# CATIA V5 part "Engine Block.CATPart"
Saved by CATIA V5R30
Part number: Part1
Bounding box of the stored display mesh (mm): x 0 to 150, y 0 to 40, z 0 to 43
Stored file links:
  D:\PROJECTS\CATIA V56R 2020\Resources\Tutorial Files\c19_catia_v5_6r2019_tut\C19_tut_04.CATPart\Engine Block.CATPart
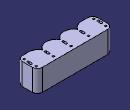
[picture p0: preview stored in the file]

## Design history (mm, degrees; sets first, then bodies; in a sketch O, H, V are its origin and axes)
Body1 (main body)
  Sketch1 on xy-plane, origin (0, 0, 0), H (1, 0, 0), V (0, 1, 0)
    line L1 (10, 0) -> (140, 0)
    line L2 (150, 10) -> (150, 30)
    line L3 (140, 40) -> (10, 40)
    line L4 (0, 30) -> (0, 10)
    arc A1 centre (10, 10) radius 10 from (10, 0) to (0, 10) cw
    arc A2 centre (140, 10) radius 10 from (140, 0) to (150, 10) ccw
    arc A3 centre (140, 30) radius 10 from (150, 30) to (140, 40) ccw
    arc A4 centre (10, 30) radius 10 from (10, 40) to (0, 30) ccw
    radius A1 = 10
    radius A2 = 10
    radius A3 = 10
    radius A4 = 10
    distance L2 L4 = 150
    distance L3 L1 = 40
    horizontal: L1 H, L3 H
    vertical: L2 V, L4 V
    coincidence: L1 O, L4 O
    tangency: A1 L1, A1 L4, A2 L1, A2 L2, A3 L2, A3 L3, A4 L3, A4 L4
  Pad1: profile Sketch1, direction (0, 0, 1), length 43
  Sketch2 on xy-plane, origin (0, 0, 0), H (1, 0, 0), V (0, 1, 0)
    circle A1 centre (22.5, 20) radius 12.5
    point P1 (22.5, 20)
    point P2 (57.5, 20)
    circle A2 centre (57.5, 20) radius 12.5
    point P3 (92.5, 20)
    circle A3 centre (92.5, 20) radius 12.5
    point P4 (127.5, 20)
    circle A4 centre (127.5, 20) radius 12.5
    reference projected line E1 (140, 40) -> (10, 40) from edge [face of Pad1 from Sketch1.L3 | end face of Pad1]
    construction line L1 (22.5, 20) -> (160.4972, 20)
    axis line L2 (75, 83.7885) -> (75, -11.6317)
    reference projected line E2 (150, 10) -> (150, 30) from edge [face of Pad1 from Sketch1.L2 | end face of Pad1]
    reference projected line E3 (0, 30) -> (0, 10) from edge [face of Pad1 from Sketch1.L4 | end face of Pad1]
    radius A2 = 12.5
    radius A3 = 12.5
    radius A4 = 12.5
    distance P1 E1 = 20
    distance P1 P2 = 35
    distance P2 P3 = 35
    distance P3 P4 = 35
    horizontal: L1 H
    coincidence: L1 P2, L1 P3, P4 L1
    symmetry: E2 E3 L2, A4 A1 L2
  Pocket1: profile Sketch2, direction (0, 0, 1), length 40
  Sketch3 on start face of Pad1, origin (0, 0, 0), H (1, 0, 0), V (0, -1, 0)
    arc A1 centre (22.5, -20) radius 20 from (40, -10.3175) to (22.4999, 0) ccw
    arc A2 centre (57.5, -20) radius 20 from (57.5, 0) to (40, -10.3175) ccw
    reference projected circle E1 centre (57.5, -20) radius 12.5 from edge [face of Pocket1 from Sketch2.A2 | start face of Pad1]
    reference projected circle E2 centre (22.5, -20) radius 12.5 from edge [face of Pocket1 from Sketch2.A1 | start face of Pad1]
    line L1 (22.4999, 0) -> (57.5, 0)
    radius A1 = 20
    radius A2 = 20
    concentricity: A2 E1, E2 A1
    fix: L1
  Pocket2: profile Sketch3, direction (0, 0, 1), through (limit type 6)
  RectPattern1: of Pocket2, direction 1 instances 3, spacing 35, along edge [start face of Pad1 | face of Pad1 from Sketch1.L1]
  Sketch4 on start face of Pad1, origin (0, 0, 0), H (1, 0, 0), V (0, -1, 0)
    circle A1 centre (6, -32) radius 2
    point P2 (40, -32)
    circle A2 centre (40, -32) radius 2
    point P3 (75, -32)
    circle A3 centre (75, -32) radius 2
    point P4 (110, -32)
    circle A4 centre (110, -32) radius 2
    circle A5 centre (144, -32) radius 2
    construction line L1 (6, -32) -> (144, -32)
    construction line L2 (40, 4.6658) -> (40, -59.1562)
    reference projected point E1 (40, -10.3175) from vertex [start face of Pad1 | face of Pocket2 from Sketch3.A2 | face of Pocket2 from Sketch3.A1]
    construction line L3 (110, 9.612) -> (110, -55.4864)
    construction line L4 (75, 52.0631) -> (75, -75.4722)
    reference projected line E2 (0, -30) -> (0, -10) from edge [start face of Pad1 | face of Pad1 from Sketch1.L4]
    reference projected line E3 (150, -10) -> (150, -30) from edge [start face of Pad1 | face of Pad1 from Sketch1.L2]
    reference projected point E4 (110, -10.3175) from vertex [face of RectPattern1 | face of RectPattern1 | start face of Pad1]
    axis line L5 (-9.2648, -20) -> (155.2665, -20)
    reference projected line E5 (10, 0) -> (140, 0) from edge [start face of Pad1 | face of Pad1 from Sketch1.L1]
    reference projected line E6 (140, -40) -> (10, -40) from edge [start face of Pad1 | face of Pad1 from Sketch1.L3]
    circle A6 centre (6, -8) radius 2
    circle A7 centre (144, -8) radius 2
    radius A1 = 2
    radius A2 = 2
    radius A3 = 2
    radius A4 = 2
    horizontal: L1 H, L5 H
    coincidence: P4 L1, P3 L1, P2 L1, L2 E1, P2 L2, P4 L3, P3 L4, L3 E4
    vertical: L2 V, L3 V, L4 V
    symmetry: E2 E3 L4, A1 A5 L4, E5 E6 L5, A1 A6 L5, A5 A7 L5
    fix: A1
  Pocket3: profile Sketch4, direction (0, 0, 1), through (limit type 6)
  Sketch5 on start face of Pad1, origin (0, 0, 0), H (1, 0, 0), V (0, -1, 0)
    construction line L1 (40, -22.3175) -> (40, -16.3175)
    point P2 (40, -16.3175)
    line L2 (38, -22.3175) -> (38, -16.3175)
    line L3 (42, -16.3175) -> (42, -22.3175)
    arc A1 centre (40, -16.3175) radius 2 from (38, -16.3175) to (42, -16.3175) cw
    arc A2 centre (40, -22.3175) radius 2 from (42, -22.3175) to (38, -22.3175) cw
    point P3 (38, -22.3175)
    point P4 (38, -16.3175)
    point P5 (42, -16.3175)
    point P6 (42, -22.3175)
    reference projected point E1 (40, -10.3175) from vertex [start face of Pad1 | face of Pocket2 from Sketch3.A2 | face of Pocket2 from Sketch3.A1]
    reference projected point E2 (40, -10.3175) from vertex [start face of Pad1 | face of Pocket2 from Sketch3.A2 | face of Pocket2 from Sketch3.A1]
    point P7 (75, -16.3175)
    point P8 (75, -22.3175)
    construction line L4 (75, -22.3175) -> (75, -16.3175)
    point P9 (73, -22.3175)
    point P10 (73, -16.3175)
    point P11 (77, -16.3175)
    point P12 (77, -22.3175)
    line L5 (73, -22.3175) -> (73, -16.3175)
    line L6 (77, -16.3175) -> (77, -22.3175)
    arc A3 centre (75, -16.3175) radius 2 from (73, -16.3175) to (77, -16.3175) cw
    arc A4 centre (75, -22.3175) radius 2 from (77, -22.3175) to (73, -22.3175) cw
    reference projected point E3 (75, -10.3175) from vertex [face of RectPattern1 | face of RectPattern1 | start face of Pad1]
    construction line L7 (110, -22.3175) -> (110, -16.3175)
    point P15 (112, -22.3175)
    point P16 (112, -16.3175)
    point P17 (108, -16.3175)
    point P18 (108, -22.3175)
    line L8 (112, -22.3175) -> (112, -16.3175)
    line L9 (108, -16.3175) -> (108, -22.3175)
    arc A5 centre (110, -16.3175) radius 2 from (112, -16.3175) to (108, -16.3175) ccw
    arc A6 centre (110, -22.3175) radius 2 from (108, -22.3175) to (112, -22.3175) ccw
    reference projected point E4 (75, -10.3175) from vertex [face of RectPattern1 | face of RectPattern1 | start face of Pad1]
    axis line L10 (40, -22.3175) -> (110, -22.3175)
    construction line L11 (5, -22.3175) -> (5, -16.3175)
    point P21 (7, -22.3175)
    point P22 (7, -16.3175)
    point P23 (3, -16.3175)
    point P24 (3, -22.3175)
    line L12 (7, -22.3175) -> (7, -16.3175)
    line L13 (3, -16.3175) -> (3, -22.3175)
    arc A7 centre (5, -16.3175) radius 2 from (7, -16.3175) to (3, -16.3175) ccw
    arc A8 centre (5, -22.3175) radius 2 from (3, -22.3175) to (7, -22.3175) ccw
    construction line L14 (145, -22.3175) -> (145, -16.3175)
    point P27 (147, -22.3175)
    point P28 (147, -16.3175)
    point P29 (143, -16.3175)
    point P30 (143, -22.3175)
    line L15 (147, -22.3175) -> (147, -16.3175)
    line L16 (143, -16.3175) -> (143, -22.3175)
    arc A9 centre (145, -16.3175) radius 2 from (147, -16.3175) to (143, -16.3175) ccw
    arc A10 centre (145, -22.3175) radius 2 from (143, -22.3175) to (147, -22.3175) ccw
    distance L1 L2 = 2
    length L1 = 6
    distance P2 E2 = 6
    distance P7 E4 = 6
    radius A3 = 2
    distance L5 L6 = 4
    vertical: L1 V
    tangency: A1 L2, A2 L2, A1 L3, A2 L3
    coincidence: L1 E1, L4 E3, L10 P8
    symmetry: L1 L7 L4, P3 P15 L4, P4 P16 L4, P5 P17 L4, P6 P18 L4, L2 L8 L4, L3 L9 L4, A1 A5 L4, A2 A6 L4, L4 L11 L1, P9 P21 L1, P10 P22 L1, P11 P23 L1, P12 P24 L1, L5 L12 L1, L6 L13 L1, A3 A7 L1, A4 A8 L1, L4 L14 L7, P9 P27 L7, P10 P28 L7, P11 P29 L7, P12 P30 L7, L5 L15 L7, L6 L16 L7, A3 A9 L7, A4 A10 L7
    horizontal: L10 H
  Pocket4: profile Sketch5, direction (0, 0, 1), through (limit type 6)
  Sketch6 on start face of Pad1, origin (0, 0, 0), H (1, 0, 0), V (0, -1, 0)
    construction line L1 (-2.1155, -20) -> (152.3983, -20)
    reference projected line E1 (10, 0) -> (140, 0) from edge [start face of Pad1 | face of Pad1 from Sketch1.L1]
    reference projected line E2 (140, -40) -> (10, -40) from edge [start face of Pad1 | face of Pad1 from Sketch1.L3]
    circle A1 centre (22, -4) radius 1.5
    point P3 (22, -4)
    circle A2 centre (22, -36) radius 1.5
    construction line L2 (40, 18.8361) -> (40, -51.6721)
    reference projected point E3 (40, -10.3175) from vertex [start face of Pad1 | face of RectPattern1 | face of Pocket2 from Sketch3.A1]
    circle A3 centre (58, -4) radius 1.5
    axis line L3 (75, 12.6867) -> (75, -50.2038)
    reference projected point E4 (75, -10.3175) from vertex [face of RectPattern1 | face of RectPattern1 | start face of Pad1]
    circle A4 centre (58, -36) radius 1.5
    circle A5 centre (128, -4) radius 1.5
    circle A6 centre (128, -36) radius 1.5
    circle A7 centre (92, -36) radius 1.5
    circle A8 centre (92, -4) radius 1.5
    radius A1 = 1.5
    distance P3 V = 22
    distance P3 L1 = 16
    horizontal: L1 H
    symmetry: E1 E2 L1, A1 A2 L1, A1 A3 L2, A2 A4 L2, A1 A5 L3, A2 A6 L3, A4 A7 L3, A3 A8 L3
    vertical: L2 V, L3 V
    coincidence: E3 L2, L3 E4
  Pocket5: profile Sketch6, direction (0, 0, 1), length 10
